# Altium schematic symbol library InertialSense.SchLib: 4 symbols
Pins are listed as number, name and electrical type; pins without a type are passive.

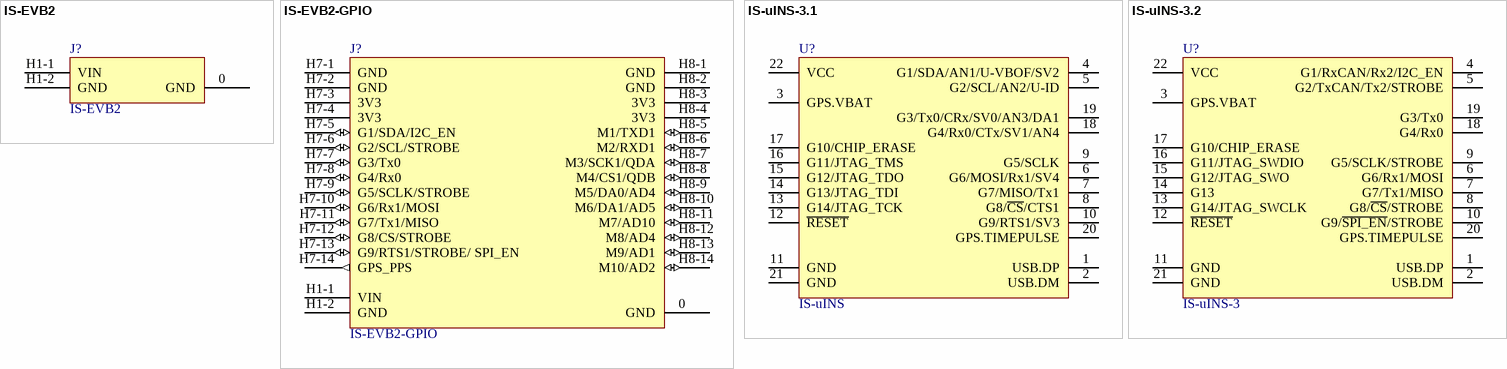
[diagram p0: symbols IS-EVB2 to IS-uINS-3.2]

## IS-EVB2
designator J?
Inertial Sense EVB 2.x
footprint EVB-2_1 (EVB 2 Footprint)
pins: 0 GND (power), H1-1 VIN (power), H1-2 GND (power)

## IS-EVB2-GPIO
designator J?
Inertial Sense EVB 2.x with GPIO connections
footprint EVB-2_1-GPIO (EVB 2.0 Footprint with GPIO headers)
pins: 0 GND (power), H1-1 VIN (power), H1-2 GND (power), H7-1 GND (power), H7-2 GND (power), H7-3 3V3 (power), H7-4 3V3 (power), H7-5 G1/SDA/I2C_EN (io), H7-6 G2/SCL/STROBE (io), H7-7 G3/Tx0 (io), H7-8 G4/Rx0 (io), H7-9 G5/SCLK/STROBE (io), H7-10 G6/Rx1/MOSI (io), H7-11 G7/Tx1/MISO (io), H7-12 G8/CS/STROBE (io), H7-13 G9/RTS1/STROBE/ SPI_EN (io), H7-14 GPS_PPS (out), H8-1 GND (power), H8-2 GND (power), H8-3 3V3 (power), H8-4 3V3 (power), H8-5 M1/TXD1 (io), H8-6 M2/RXD1 (io), H8-7 M3/SCK1/QDA (io), H8-8 M4/CS1/QDB (io), H8-9 M5/DA0/AD4 (io), H8-10 M6/DA1/AD5 (io), H8-11 M7/AD10 (io), H8-12 M8/AD4 (io), H8-13 M9/AD1 (io), H8-14 M10/AD2 (io)

## IS-uINS-3.1
designator U?, comment Manufacturer Part Number: IS-uINS  (hidden comment: uINS)
Inertial Sense uINS
footprint IS-uINS-3.2_no_paste (Inerial Sense uINS r3.2, 22pins 1.27mm pitch)
pins: 1 USB.DP, 2 USB.DM, 3 GPS.VBAT, 4 G1/SDA/AN1/U-VBOF/SV2, 5 G2/SCL/AN2/U-ID, 6 G6/MOSI/Rx1/SV4, 7 G7/MISO/Tx1, 8 G8/~{CS}/CTS1, 9 G5/SCLK, 10 G9/RTS1/SV3, 11 GND (power), 12 ~{RESET}, 13 G14/JTAG_TCK, 14 G13/JTAG_TDI, 15 G12/JTAG_TDO, 16 G11/JTAG_TMS, 17 G10/CHIP_ERASE, 18 G4/Rx0/CTx/SV1/AN4, 19 G3/Tx0/CRx/SV0/AN3/DA1, 20 GPS.TIMEPULSE, 21 GND (power), 22 VCC (power)

## IS-uINS-3.2
designator U?, comment Manufacturer Part Number: IS-uINS-3  (hidden comment: uINS)
Inertial Sense uINS
footprint IS-uINS-3.2_no_paste (Inerial Sense uINS r3.2, 22pins 1.27mm pitch)
pins: 1 USB.DP, 2 USB.DM, 3 GPS.VBAT, 4 G1/RxCAN/Rx2/I2C_EN, 5 G2/TxCAN/Tx2/STROBE, 6 G6/Rx1/MOSI, 7 G7/Tx1/MISO, 8 G8/~{CS}/STROBE, 9 G5/SCLK/STROBE, 10 G9/~{SPI_EN}/STROBE, 11 GND (power), 12 ~{RESET}, 13 G14/JTAG_SWCLK, 14 G13, 15 G12/JTAG_SWO, 16 G11/JTAG_SWDIO, 17 G10/CHIP_ERASE, 18 G4/Rx0, 19 G3/Tx0, 20 GPS.TIMEPULSE, 21 GND (power), 22 VCC (power)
